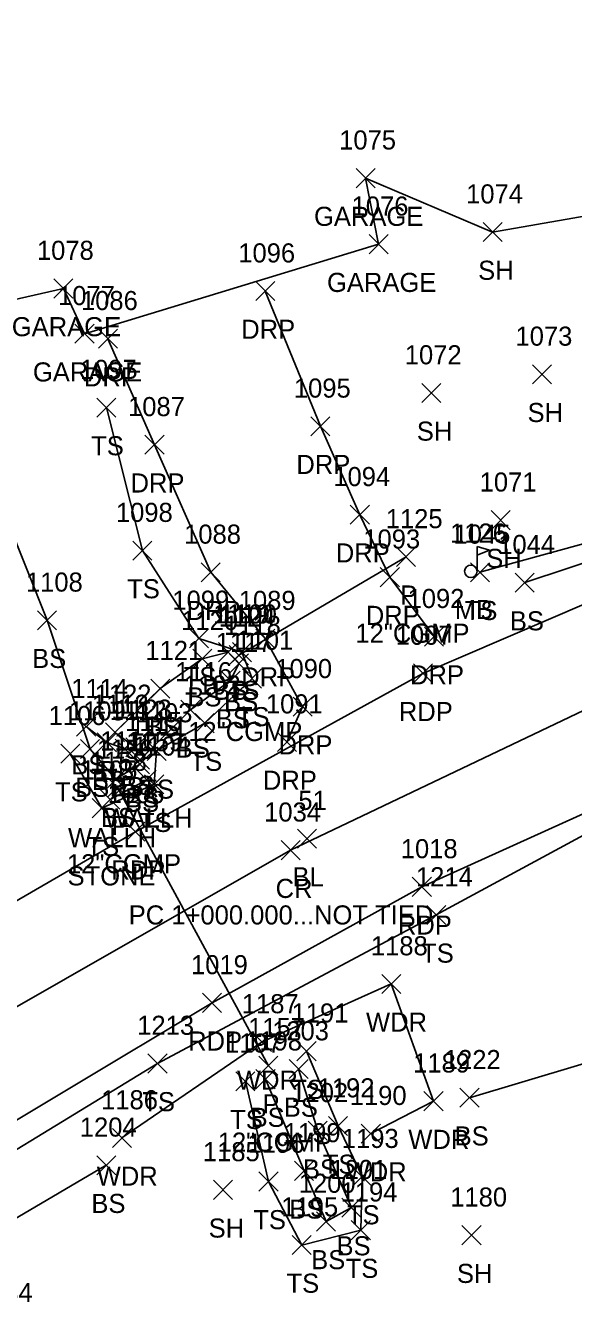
# Model space of a CAD drawing. Extents: x 1526508 to 1531550, y 369926 to 373082.
# Drawn here: x 1530836 to 1530893.3, y 370047.9 to 370183.1 of the extents above; entities that cross this region are included whole.
import ezdxf

# ---------------------------------------------------------------- set-up
doc = ezdxf.new("R2010")
doc.units = 0
for name, color, linetype in [('C_A', 7, 'Continuous'), ('C_C', 7, 'Continuous'), ('C_I', 7, 'Continuous'), ('C_TIC', 7, 'Continuous'), ('D_A', 7, 'Continuous'), ('D_C', 7, 'Continuous'), ('D_I', 7, 'Continuous'), ('D_TIC', 7, 'Continuous'), ('DCP', 7, 'Continuous'), ('DHW', 7, 'Continuous'), ('L_A', 7, 'Continuous'), ('L_I', 7, 'Continuous'), ('L_TIC', 7, 'Continuous'), ('LAWA', 7, 'Continuous'), ('LBC', 7, 'Continuous'), ('LELB', 7, 'Continuous'), ('LMB', 7, 'Continuous'), ('LSOGP', 7, 'Continuous'), ('P_A', 7, 'Continuous'), ('P_I', 7, 'Continuous'), ('P_TIC', 7, 'Continuous'), ('PET', 7, 'Continuous'), ('PRC', 7, 'Continuous'), ('R_A', 7, 'Continuous'), ('R_I', 7, 'Continuous'), ('R_TIC', 7, 'Continuous'), ('RDP', 7, 'Continuous')]:
    doc.layers.add(name, color=color, linetype=linetype)

msp = doc.modelspace()

# ---------------------------------------------------------------- linework, layer by layer
at = {"layer": 'C_TIC'}
for points in [[(1530864.43, 370096.95), (1530866.43, 370098.95)], [(1530866.43, 370096.95), (1530864.43, 370098.95)]]:
    msp.add_lwpolyline(points, dxfattribs=at)
at = {"layer": 'D_TIC'}
for points in [[(1530874.8, 370126.46), (1530876.8, 370128.46)], [(1530876.8, 370126.46), (1530874.8, 370128.46)], [(1530857.3, 370116.16), (1530859.3, 370118.16)], [(1530859.3, 370116.16), (1530857.3, 370118.16)], [(1530847.65, 370103.1), (1530849.65, 370105.1)], [(1530849.65, 370103.1), (1530847.65, 370105.1)], [(1530844.6, 370102.31), (1530846.6, 370104.31)], [(1530846.6, 370102.31), (1530844.6, 370104.31)], [(1530843.83, 370101.04), (1530845.83, 370103.04)], [(1530845.83, 370101.04), (1530843.83, 370103.04)], [(1530860.39, 370073.15), (1530862.39, 370075.15)], [(1530862.39, 370073.15), (1530860.39, 370075.15)]]:
    msp.add_lwpolyline(points, dxfattribs=at)
at = {"layer": 'DCP'}
for points in [[(1530858.3, 370117.16), (1530875.8, 370127.46)], [(1530845.6, 370103.31), (1530861.39, 370074.15)]]:
    msp.add_lwpolyline(points, dxfattribs=at)
at = {"layer": 'DHW'}
msp.add_lwpolyline([(1530844.83, 370102.04), (1530848.65, 370104.1)], dxfattribs=at)
at = {"layer": 'L_TIC'}
for points in [[(1530870.57, 370166.13), (1530872.57, 370168.13)], [(1530872.57, 370166.13), (1530870.57, 370168.13)], [(1530883.86, 370160.48), (1530885.86, 370162.48)], [(1530885.86, 370160.48), (1530883.86, 370162.48)], [(1530871.93, 370159.21), (1530873.93, 370161.21)], [(1530873.93, 370159.21), (1530871.93, 370161.21)], [(1530838.93, 370154.57), (1530840.93, 370156.57)], [(1530840.93, 370154.57), (1530838.93, 370156.57)], [(1530841.14, 370149.83), (1530843.14, 370151.83)], [(1530843.14, 370149.83), (1530841.14, 370151.83)], [(1530889.03, 370145.58), (1530891.03, 370147.58)], [(1530891.03, 370145.58), (1530889.03, 370147.58)], [(1530877.44, 370143.63), (1530879.44, 370145.63)], [(1530879.44, 370143.63), (1530877.44, 370145.63)], [(1530843.43, 370142.1), (1530845.43, 370144.1)], [(1530845.43, 370142.1), (1530843.43, 370144.1)], [(1530884.71, 370130.3), (1530886.71, 370132.3)], [(1530886.71, 370130.3), (1530884.71, 370132.3)], [(1530847.2, 370127.12), (1530849.2, 370129.12)], [(1530849.2, 370127.12), (1530847.2, 370129.12)], [(1530882.54, 370124.84), (1530884.54, 370126.84)], [(1530884.54, 370124.84), (1530882.54, 370126.84)], [(1530887.23, 370123.76), (1530889.23, 370125.76)], [(1530889.23, 370123.76), (1530887.23, 370125.76)], [(1530837.22, 370119.82), (1530839.22, 370121.82)], [(1530839.22, 370119.82), (1530837.22, 370121.82)], [(1530853.12, 370117.92), (1530855.12, 370119.92)], [(1530855.12, 370117.92), (1530853.12, 370119.92)], [(1530853.47, 370115.79), (1530855.47, 370117.79)], [(1530855.47, 370115.79), (1530853.47, 370117.79)], [(1530856.18, 370116.48), (1530858.18, 370118.48)], [(1530858.18, 370116.48), (1530856.18, 370118.48)], [(1530857.31, 370115.29), (1530859.31, 370117.29)], [(1530859.31, 370115.29), (1530857.31, 370117.29)], [(1530857.62, 370116.48), (1530859.62, 370118.48)], [(1530859.62, 370116.48), (1530857.62, 370118.48)], [(1530849.07, 370112.66), (1530851.07, 370114.66)], [(1530851.07, 370112.66), (1530849.07, 370114.66)], [(1530856.44, 370113.5), (1530858.44, 370115.5)], [(1530858.44, 370113.5), (1530856.44, 370115.5)], [(1530858.68, 370113.72), (1530860.68, 370115.72)], [(1530860.68, 370113.72), (1530858.68, 370115.72)], [(1530852.24, 370110.43), (1530854.24, 370112.43)], [(1530854.24, 370110.43), (1530852.24, 370112.43)], [(1530841.31, 370108.68), (1530843.31, 370110.68)], [(1530843.31, 370108.68), (1530841.31, 370110.68)], [(1530853.73, 370109.04), (1530855.73, 370111.04)], [(1530855.73, 370109.04), (1530853.73, 370111.04)], [(1530844.33, 370108.07), (1530846.33, 370110.07)], [(1530846.33, 370108.07), (1530844.33, 370110.07)], [(1530839.65, 370105.84), (1530841.65, 370107.84)], [(1530841.65, 370105.84), (1530839.65, 370107.84)], [(1530841.72, 370106.32), (1530843.72, 370108.32)], [(1530843.72, 370106.32), (1530841.72, 370108.32)], [(1530843.48, 370107.02), (1530845.48, 370109.02)], [(1530845.48, 370107.02), (1530843.48, 370109.02)], [(1530845.34, 370106.37), (1530847.34, 370108.37)], [(1530847.34, 370106.37), (1530845.34, 370108.37)], [(1530846.46, 370106.51), (1530848.46, 370108.51)], [(1530848.46, 370106.51), (1530846.46, 370108.51)], [(1530848.69, 370106.13), (1530850.69, 370108.13)], [(1530850.69, 370106.13), (1530848.69, 370108.13)], [(1530846.94, 370104.74), (1530848.94, 370106.74)], [(1530848.94, 370104.74), (1530846.94, 370106.74)], [(1530846.96, 370105.21), (1530848.96, 370107.21)], [(1530848.96, 370105.21), (1530846.96, 370107.21)], [(1530844.43, 370103.17), (1530846.43, 370105.17)], [(1530846.43, 370103.17), (1530844.43, 370105.17)], [(1530848.43, 370102.64), (1530850.43, 370104.64)], [(1530850.43, 370102.64), (1530848.43, 370104.64)], [(1530842.94, 370100.13), (1530844.94, 370102.13)], [(1530844.94, 370100.13), (1530842.94, 370102.13)], [(1530877.97, 370088.95), (1530879.97, 370090.95)], [(1530879.97, 370088.95), (1530877.97, 370090.95)], [(1530873.25, 370081.72), (1530875.25, 370083.72)], [(1530875.25, 370081.72), (1530873.25, 370083.72)], [(1530859.73, 370075.65), (1530861.73, 370077.65)], [(1530861.73, 370075.65), (1530859.73, 370077.65)], [(1530864.38, 370074.68), (1530866.38, 370076.68)], [(1530866.38, 370074.68), (1530864.38, 370076.68)], [(1530848.78, 370073.39), (1530850.78, 370075.39)], [(1530850.78, 370073.39), (1530848.78, 370075.39)], [(1530863.56, 370072.81), (1530865.56, 370074.81)], [(1530865.56, 370072.81), (1530863.56, 370074.81)], [(1530857.98, 370071.53), (1530859.98, 370073.53)], [(1530859.98, 370071.53), (1530857.98, 370073.53)], [(1530860.09, 370071.75), (1530862.09, 370073.75)], [(1530862.09, 370071.75), (1530860.09, 370073.75)], [(1530877.68, 370069.44), (1530879.68, 370071.44)], [(1530879.68, 370069.44), (1530877.68, 370071.44)], [(1530881.45, 370069.8), (1530883.45, 370071.8)], [(1530883.45, 370069.8), (1530881.45, 370071.8)], [(1530867.68, 370066.84), (1530869.68, 370068.84)], [(1530869.68, 370066.84), (1530867.68, 370068.84)], [(1530845.06, 370065.59), (1530847.06, 370067.59)], [(1530847.06, 370065.59), (1530845.06, 370067.59)], [(1530865.56, 370066.34), (1530867.56, 370068.34)], [(1530867.56, 370066.34), (1530865.56, 370068.34)], [(1530871.12, 370066.04), (1530873.12, 370068.04)], [(1530873.12, 370066.04), (1530871.12, 370068.04)], [(1530843.42, 370062.73), (1530845.42, 370064.73)], [(1530845.42, 370062.73), (1530843.42, 370064.73)], [(1530864.13, 370062.14), (1530866.13, 370064.14)], [(1530866.13, 370062.14), (1530864.13, 370064.14)], [(1530870.21, 370061.54), (1530872.21, 370063.54)], [(1530872.21, 370061.54), (1530870.21, 370063.54)], [(1530855.65, 370060.15), (1530857.65, 370062.15)], [(1530857.65, 370060.15), (1530855.65, 370062.15)], [(1530860.4, 370061.03), (1530862.4, 370063.03)], [(1530862.4, 370061.03), (1530860.4, 370063.03)], [(1530869.08, 370058.29), (1530871.08, 370060.29)], [(1530871.08, 370058.29), (1530869.08, 370060.29)], [(1530866.43, 370056.84), (1530868.43, 370058.84)], [(1530868.43, 370056.84), (1530866.43, 370058.84)], [(1530870.07, 370055.93), (1530872.07, 370057.93)], [(1530872.07, 370055.93), (1530870.07, 370057.93)], [(1530863.88, 370054.37), (1530865.88, 370056.37)], [(1530865.88, 370054.37), (1530863.88, 370056.37)], [(1530881.65, 370055.4), (1530883.65, 370057.4)], [(1530883.65, 370055.4), (1530881.65, 370057.4)]]:
    msp.add_lwpolyline(points, dxfattribs=at)
at = {"layer": 'LAWA'}
msp.add_lwpolyline([(1530846.06, 370066.59), (1530860.73, 370076.65), (1530874.25, 370082.72), (1530878.68, 370070.44), (1530872.12, 370067.04)], dxfattribs=at)
at = {"layer": 'LBC'}
msp.add_lwpolyline([(1530871.57, 370167.13), (1530872.93, 370160.21), (1530842.14, 370150.83), (1530839.93, 370155.57)], dxfattribs=at)
at = {"layer": 'LELB'}
for points in [[(1530883.54, 370125.84), (1530896.12, 370129.31), (1530911.8, 370134.99), (1530934.8, 370141.1), (1530961.14, 370145.47), (1530991.24, 370149.13)], [(1530991.34, 370146.7), (1530961.31, 370142.81), (1530935.97, 370139.44), (1530906.69, 370130.9), (1530888.23, 370124.76)], [(1530844.43, 370143.1), (1530848.2, 370128.12), (1530854.12, 370118.92), (1530858.62, 370117.48), (1530859.68, 370114.72), (1530854.73, 370110.04), (1530849.69, 370107.13), (1530849.43, 370103.64), (1530843.94, 370101.13), (1530840.65, 370106.84)], [(1530831.81, 370136.85), (1530838.22, 370120.82), (1530842.72, 370107.32), (1530845.43, 370104.17), (1530847.94, 370105.74), (1530846.34, 370107.37), (1530844.48, 370108.02), (1530842.31, 370109.68)], [(1530847.96, 370106.21), (1530853.24, 370111.43), (1530857.44, 370114.5), (1530858.31, 370116.29), (1530857.18, 370117.48), (1530854.47, 370116.79), (1530850.07, 370113.66), (1530845.33, 370109.07), (1530847.46, 370107.51)], [(1530685.88, 369975.28), (1530717.44, 369995.35), (1530750.55, 370015.24), (1530789.81, 370037.94), (1530822.42, 370057.69), (1530849.78, 370074.39), (1530878.97, 370089.95), (1530906.44, 370104.85), (1530934.55, 370113.45), (1530953.41, 370116.76)], [(1530905.42, 370077.67), (1530882.45, 370070.8)], [(1530865.38, 370075.68), (1530868.68, 370067.84), (1530871.21, 370062.54), (1530871.07, 370056.93), (1530864.88, 370055.37), (1530861.4, 370062.03), (1530858.98, 370072.53)], [(1530861.09, 370072.75), (1530865.13, 370063.14), (1530867.43, 370057.84), (1530870.08, 370059.29), (1530866.56, 370067.34), (1530864.56, 370073.81)], [(1530844.42, 370063.73), (1530824.69, 370052.16), (1530807.15, 370037.79), (1530797.3, 370033.58)]]:
    msp.add_lwpolyline(points, dxfattribs=at)
at = {"layer": 'LMB'}
for p, q in [((1530883.24, 370128.55), (1530884.54, 370128.17)), ((1530883.25, 370125.96), (1530883.25, 370128.56)), ((1530883.25, 370127.65), (1530884.53, 370128.16)), ((1530882.59, 370125.95), (1530882.59, 370125.95))]:
    msp.add_line(p, q, dxfattribs=at)
msp.add_circle((1530882.59, 370125.95), 0.656, dxfattribs=at)
at = {"layer": 'LSOGP'}
msp.add_lwpolyline([(1530986.53, 370183.09), (1530962.18, 370174.64), (1530928.42, 370177.02), (1530910.89, 370166.02), (1530884.86, 370161.48), (1530871.57, 370167.13), (1530872.93, 370160.21), (1530842.14, 370150.83), (1530839.93, 370155.57), (1530813.18, 370149.48)], dxfattribs=at)
at = {"layer": 'P_TIC'}
for points in [[(1530876.57, 370114.25), (1530878.57, 370116.25)], [(1530878.57, 370114.25), (1530876.57, 370116.25)], [(1530846.47, 370097.66), (1530848.47, 370099.66)], [(1530848.47, 370097.66), (1530846.47, 370099.66)], [(1530862.72, 370095.73), (1530864.72, 370097.73)], [(1530864.72, 370095.73), (1530862.72, 370097.73)], [(1530876.46, 370091.89), (1530878.46, 370093.89)], [(1530878.46, 370091.89), (1530876.46, 370093.89)], [(1530854.5, 370079.74), (1530856.5, 370081.74)], [(1530856.5, 370079.74), (1530854.5, 370081.74)]]:
    msp.add_lwpolyline(points, dxfattribs=at)
at = {"layer": 'PET'}
for points in [[(1530659.86, 369987.59), (1530689.68, 370004.88), (1530725.77, 370025.63), (1530760.95, 370046.59), (1530789.35, 370063.64), (1530821.52, 370083.59), (1530847.47, 370098.66), (1530877.57, 370115.25), (1530907.84, 370128.26), (1530938.81, 370136.76), (1530967.77, 370140.97), (1531005.44, 370146.08), (1531034.99, 370150.93)], [(1531038.44, 370130.38), (1531006.6, 370125.67), (1530965.47, 370120.56), (1530935.63, 370115.81), (1530906.91, 370106.24), (1530877.46, 370092.89), (1530855.5, 370080.74), (1530824.98, 370062.43), (1530800.48, 370048.15), (1530769.96, 370030.14), (1530741.1, 370012.79), (1530710.76, 369994.53), (1530684.03, 369978.66), (1530669.6, 369970.09)]]:
    msp.add_lwpolyline(points, dxfattribs=at)
at = {"layer": 'PRC'}
msp.add_lwpolyline([(1530664.43, 369978.53), (1530688.65, 369992.9), (1530715.76, 370008.79), (1530744.4, 370025.81), (1530774.39, 370044.32), (1530799.13, 370059.29), (1530828.47, 370076.59), (1530863.72, 370096.73), (1530899.64, 370113.89), (1530935.78, 370125.96), (1530974.77, 370132.27), (1531009.67, 370136.56), (1531036.22, 370140.48)], dxfattribs=at)
at = {"layer": 'R_TIC'}
for points in [[(1530860.07, 370154.3), (1530862.07, 370156.3)], [(1530862.07, 370154.3), (1530860.07, 370156.3)], [(1530843.59, 370149.31), (1530845.59, 370151.31)], [(1530845.59, 370149.31), (1530843.59, 370151.31)], [(1530865.84, 370140.14), (1530867.84, 370142.14)], [(1530867.84, 370140.14), (1530865.84, 370142.14)], [(1530848.47, 370138.2), (1530850.47, 370140.2)], [(1530850.47, 370138.2), (1530848.47, 370140.2)], [(1530869.96, 370130.87), (1530871.96, 370132.87)], [(1530871.96, 370130.87), (1530869.96, 370132.87)], [(1530854.35, 370124.84), (1530856.35, 370126.84)], [(1530856.35, 370124.84), (1530854.35, 370126.84)], [(1530873.1, 370124.33), (1530875.1, 370126.33)], [(1530875.1, 370124.33), (1530873.1, 370126.33)], [(1530860.07, 370117.9), (1530862.07, 370119.9)], [(1530862.07, 370117.9), (1530860.07, 370119.9)], [(1530877.73, 370118.1), (1530879.73, 370120.1)], [(1530879.73, 370118.1), (1530877.73, 370120.1)], [(1530863.97, 370110.76), (1530865.97, 370112.76)], [(1530865.97, 370110.76), (1530863.97, 370112.76)], [(1530862.33, 370107.06), (1530864.33, 370109.06)], [(1530864.33, 370107.06), (1530862.33, 370109.06)]]:
    msp.add_lwpolyline(points, dxfattribs=at)
at = {"layer": 'RDP'}
for points in [[(1530878.73, 370119.1), (1530874.1, 370125.33), (1530870.96, 370131.87), (1530866.84, 370141.14), (1530861.07, 370155.3)], [(1530844.59, 370150.31), (1530849.47, 370139.2), (1530855.35, 370125.84), (1530861.07, 370118.9), (1530864.97, 370111.76), (1530863.33, 370108.06)]]:
    msp.add_lwpolyline(points, dxfattribs=at)

# ---------------------------------------------------------------- texts
at = {"layer": 'C_A'}
msp.add_text('BL', height=2, dxfattribs=at).set_placement((1530863.92, 370092.95))
at = {"layer": 'C_C'}
msp.add_text('PC 1+000.000...NOT TIED', height=2, dxfattribs=at).set_placement((1530846.77, 370088.95))
at = {"layer": 'C_I'}
msp.add_text('51', height=2, dxfattribs=at).set_placement((1530864.53, 370100.95))
at = {"layer": 'D_A'}
for s, p in [('P', (1530875.18, 370122.46)), ('P', (1530857.68, 370112.16)), ('WALLH', (1530844.24, 370099.1)), ('P', (1530844.98, 370098.31)), ('WALLH', (1530840.42, 370097.04)), ('P', (1530860.77, 370069.15))]:
    msp.add_text(s, height=2, dxfattribs=at).set_placement(p)
at = {"layer": 'D_C'}
for s, p in [('12"CGMP', (1530870.5, 370118.46)), ('12"CGMP', (1530853, 370108.16)), ('12"CGMP', (1530840.3, 370094.31)), ('STONE', (1530840.37, 370093.04)), ('12"CGMP', (1530856.09, 370065.15))]:
    msp.add_text(s, height=2, dxfattribs=at).set_placement(p)
at = {"layer": 'D_I'}
for s, p in [('1125', (1530873.68, 370130.46)), ('1124', (1530856.18, 370120.16)), ('1159', (1530846.52, 370107.1)), ('1156', (1530843.42, 370106.31)), ('1158', (1530842.71, 370105.04)), ('1157', (1530859.27, 370077.15))]:
    msp.add_text(s, height=2, dxfattribs=at).set_placement(p)
at = {"layer": 'L_A'}
for s, p in [('GARAGE', (1530866.17, 370162.13)), ('SH', (1530883.35, 370156.48)), ('GARAGE', (1530867.53, 370155.21)), ('GARAGE', (1530834.53, 370150.57)), ('GARAGE', (1530836.74, 370145.83)), ('SH', (1530888.52, 370141.58)), ('SH', (1530876.93, 370139.63)), ('TS', (1530842.84, 370138.1)), ('SH', (1530884.2, 370126.3)), ('TS', (1530846.61, 370123.12)), ('MB', (1530880.9, 370120.95)), ('TS', (1530881.95, 370120.84)), ('BS', (1530886.67, 370119.76)), ('BS', (1530836.66, 370115.82)), ('TS', (1530852.53, 370113.92)), ('BS', (1530855.62, 370112.48)), ('TS', (1530857.03, 370112.48)), ('BS', (1530852.91, 370111.79)), ('BS', (1530856.75, 370111.29)), ('TS', (1530858.09, 370109.72)), ('BS', (1530848.51, 370108.66)), ('BS', (1530855.88, 370109.5)), ('BS', (1530851.69, 370106.43)), ('BS', (1530840.75, 370104.68)), ('TS', (1530853.14, 370105.04)), ('BS', (1530842.92, 370103.02)), ('BS', (1530843.77, 370104.07)), ('TS', (1530839.06, 370101.84)), ('BS', (1530841.16, 370102.32)), ('BS', (1530844.78, 370102.37)), ('BS', (1530845.9, 370102.51)), ('TS', (1530848.1, 370102.13)), ('BS', (1530846.38, 370100.74)), ('BS', (1530846.4, 370101.21)), ('BS', (1530843.87, 370099.17)), ('TS', (1530847.83, 370098.64)), ('TS', (1530842.35, 370096.13)), ('TS', (1530877.38, 370084.95)), ('WDR', (1530871.61, 370077.72)), ('WDR', (1530858.1, 370071.65)), ('TS', (1530863.79, 370070.68)), ('TS', (1530848.19, 370069.39)), ('BS', (1530863, 370068.81)), ('TS', (1530857.39, 370067.53)), ('BS', (1530859.53, 370067.75)), ('WDR', (1530876.04, 370065.44)), ('BS', (1530880.89, 370065.8)), ('TS', (1530867.09, 370062.84)), ('WDR', (1530843.42, 370061.59)), ('BS', (1530865, 370062.34)), ('WDR', (1530869.48, 370062.04)), ('BS', (1530842.86, 370058.73)), ('TS', (1530859.81, 370057.03)), ('BS', (1530863.57, 370058.14)), ('TS', (1530869.62, 370057.54)), ('SH', (1530855.14, 370056.15)), ('BS', (1530868.52, 370054.29)), ('BS', (1530865.87, 370052.84)), ('TS', (1530869.48, 370051.93)), ('TS', (1530863.29, 370050.37)), ('SH', (1530881.13, 370051.4))]:
    msp.add_text(s, height=2, dxfattribs=at).set_placement(p)
at = {"layer": 'L_I'}
for s, p in [('1075', (1530868.8, 370170.13)), ('1074', (1530882.09, 370164.48)), ('1076', (1530870.1, 370163.21)), ('1078', (1530837.16, 370158.57)), ('1077', (1530839.37, 370153.83)), ('1073', (1530887.26, 370149.58)), ('1072', (1530875.67, 370147.63)), ('1097', (1530841.66, 370146.1)), ('1071', (1530883.51, 370134.3)), ('1098', (1530845.43, 370131.12)), ('1126', (1530880.41, 370128.95)), ('1045', (1530880.77, 370128.84)), ('1044', (1530885.45, 370127.76)), ('1108', (1530836.01, 370123.82)), ('1099', (1530851.34, 370121.92)), ('1120', (1530852.26, 370119.79)), ('1119', (1530855.61, 370120.48)), ('1100', (1530856.33, 370120.48)), ('1118', (1530856.75, 370119.29)), ('1121', (1530848.51, 370116.66)), ('1117', (1530855.88, 370117.5)), ('1101', (1530858.04, 370117.72)), ('1116', (1530851.63, 370114.43)), ('1114', (1530840.75, 370112.68)), ('1102', (1530852.53, 370113.04)), ('1122', (1530843.2, 370112.07)), ('1106', (1530838.39, 370109.84)), ('1109', (1530840.51, 370110.32)), ('1113', (1530842.92, 370111.02)), ('1112', (1530844.78, 370110.37)), ('1123', (1530845.33, 370110.51)), ('1103', (1530847.49, 370110.13)), ('1115', (1530846.4, 370109.21)), ('1111', (1530846.95, 370108.74)), ('1110', (1530843.78, 370107.17)), ('1104', (1530847.22, 370106.64)), ('1105', (1530841.73, 370104.13)), ('1214', (1530876.84, 370092.95)), ('1188', (1530872.12, 370085.72)), ('1187', (1530858.61, 370079.65)), ('1191', (1530863.82, 370078.68)), ('1213', (1530847.66, 370077.39)), ('1203', (1530861.78, 370076.81)), ('1197', (1530856.86, 370075.53)), ('1198', (1530858.96, 370075.75)), ('1189', (1530876.55, 370073.44)), ('1222', (1530879.76, 370073.8)), ('1192', (1530866.55, 370070.84)), ('1186', (1530843.88, 370069.59)), ('1202', (1530863.79, 370070.34)), ('1190', (1530869.91, 370070.04)), ('1204', (1530841.65, 370066.73)), ('1199', (1530863, 370066.14)), ('1193', (1530869.08, 370065.54)), ('1185', (1530854.53, 370064.15)), ('1196', (1530859.22, 370065.03)), ('1201', (1530867.88, 370062.29)), ('1200', (1530864.57, 370060.84)), ('1194', (1530868.95, 370059.93)), ('1195', (1530862.75, 370058.37)), ('1180', (1530880.43, 370059.4)), ('1184', (1530830.76, 370049.41))]:
    msp.add_text(s, height=2, dxfattribs=at).set_placement(p)
at = {"layer": 'P_A'}
for s, p in [('RDP', (1530875.05, 370110.25)), ('RDP', (1530844.95, 370093.66)), ('CR', (1530862.15, 370091.73)), ('RDP', (1530874.95, 370087.89)), ('RDP', (1530852.99, 370075.74))]:
    msp.add_text(s, height=2, dxfattribs=at).set_placement(p)
at = {"layer": 'P_I'}
for s, p in [('1007', (1530874.72, 370118.25)), ('1006', (1530844.56, 370101.66)), ('1034', (1530860.95, 370099.73)), ('1018', (1530875.25, 370095.89)), ('1019', (1530853.29, 370083.74))]:
    msp.add_text(s, height=2, dxfattribs=at).set_placement(p)
at = {"layer": 'R_A'}
for p in [(1530858.55, 370150.3), (1530842.08, 370145.31), (1530864.32, 370136.14), (1530846.96, 370134.2), (1530868.45, 370126.87), (1530852.83, 370120.84), (1530871.59, 370120.33), (1530858.55, 370113.9), (1530876.22, 370114.1), (1530862.45, 370106.76), (1530860.82, 370103.06)]:
    msp.add_text('DRP', height=2, dxfattribs=at).set_placement(p)
at = {"layer": 'R_I'}
for s, p in [('1096', (1530858.24, 370158.3)), ('1086', (1530841.77, 370153.31)), ('1095', (1530864.06, 370144.14)), ('1087', (1530846.7, 370142.2)), ('1094', (1530868.19, 370134.87)), ('1088', (1530852.57, 370128.84)), ('1093', (1530871.33, 370128.33)), ('1089', (1530858.29, 370121.9)), ('1092', (1530875.96, 370122.1)), ('1090', (1530862.11, 370114.76)), ('1091', (1530861.13, 370111.06))]:
    msp.add_text(s, height=2, dxfattribs=at).set_placement(p)

doc.saveas('drawing.dxf')
